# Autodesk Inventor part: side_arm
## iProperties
Author: GJOHNST2
Shininess: 20.0
Length Units: 11272
Angle Units: 11286
Time Units: 11279
Mass Units: 11290
Length Display Precision: 3
Angle Display Precision: 2
Compacted: True
PropertySet Name: _Private Model Information
Created: 2001-11
Part Number: side_arm
Material: Stainless Steel, Austenitic
Document SubType Name: Modeling
Designer: GJOHNST2
Control State: 0
Master: False
Checked Out: False
PropertySet Name: Design Tracking Control
Density: 8.03
Volumn: 12.760621682643773
Area: 58.50553773909135
PropertySet Name: Model Information
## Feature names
1. Extrusion1
